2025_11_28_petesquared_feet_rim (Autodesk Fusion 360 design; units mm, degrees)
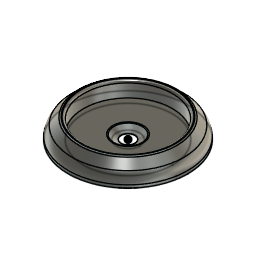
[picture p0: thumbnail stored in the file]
sketch "feet_rim" plane through (0, 0, 0) normal (0, 0, 1) x axis (1, 0, 0)
  circle C1 centre (0, 0) radius 14.732
  circle C2 centre (0, 0) radius 19.812
  circle C3 centre (0, 0) radius 2.286
  circle C4 centre (0, 0) radius 3.81
  point P1 (0, 0)
  point P2 (0, 0)
  point P4 (0, 0)
  coincident P1 P2
  concentric C1 C2
  coincident P1 P4
  concentric C1 C4
  dimension "d1" diameter C1 = 29.464
  dimension "d2" distance C1 C2 = 5.08
  dimension "d3" diameter C3 = 4.572
  dimension "d4" diameter C4 = 7.62
extrude "Extrude1" new body sketch "feet_rim" along normal blind 1.524 bodies "feet_rim"
extrude "Extrude2" add sketch "feet_rim" profile of C1 C2 along normal blind 6.604
chamfer "Chamfer1" distance 3.81
chamfer "Chamfer2" distance 2.54 distance 1.4224
fillet "Fillet1" radius 0.762 4.445
named bodies: "feet_rim"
